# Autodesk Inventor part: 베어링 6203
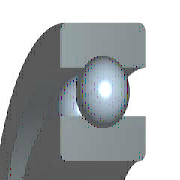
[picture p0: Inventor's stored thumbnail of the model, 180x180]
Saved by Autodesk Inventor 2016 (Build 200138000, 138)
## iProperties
IsCustomPart: 0
Created: 2016-04
Part Number: 베어링 6203
Material: 강철, 연강
Description: 깊은 그루브 볼 베어링
Document SubType Name: Modeling
Standard: KS B 2023
Designer: mdu
Standards Organization: KS
Language: ko-KR
Size Designation: 6203 - 17 x 40 x 12
Categories: <MemberInstance><Categories><Category DisplayName="샤프트 부품" InternalName="7f7aeb1f-a693-4053-b835-cee3144e0d98" Mnemonic="SHFT"><Category DisplayName="베어링" Inter
Density: 7.86 g/cm^3
Mass: 64.9809 g
Surface Area: 64.3582 cm^2
Volume: 8.26729 cm^3
Appearance: 노란색
Author: mdu
Revision Number: 1
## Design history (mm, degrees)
sketch "스케치" dims "d0" = 5.98 (= -0.26 x WD + 0.26 x BD)
  geometry: L1 (3.01, 14.25)-(8.99, 14.25); L2 (6, 14.25)-(6, 11.26); L3 (6, 14.25)-(6, 17.24); L4 (3.778, 12.249)-(0, 12.249); L5 (0, 8.5)-(12, 8.5); L6 (3.778, 16.251)-(0, 16.251); L7 (0, 20)-(12, 20); L8 (12, 8.5)-(12, 12.249); L9 (8.222, 12.249)-(12, 12.249); L10 (8.222, 16.251)-(12, 16.251); L11 (12, 20)-(12, 16.251); L12 (-1.4, 0)-(8.4, 0) reference; L13 (0, -0.3)-(0, 5.3) reference
  constraints: 22 end point, 4 point on line, 2 collinear, 2 perpendicular, 2 symmetric about line, 1 midpoint, 1 parallel, 14 other
  dimensions: "d9" = 17 diameter of L5 L12 (= WD); "d11" = 40 diameter of L7 L12 (= BD); "d12" = 12 distance between parallel lines of L8 L13 (= KB); "d13" = 24.498 diameter of L9 L12 (= 0.326 x BD + 0.674 x WD)
revolve "본체" stored, may be unused: angle "d6" = 90 deg
revolve "볼" stored, may be unused: angle "d7" = 90 deg
pattern_circular "IDS_ARRAYBALL[SIMPL:T]" dims angle "d3" = 360 deg
body "Solid1"
fillet "모깎기1" dims "d1" = 0.6 (= KRS)
other parameters: "WD" = 17 [user parameter; used in 5 equation terms], "BD" = 40 [user parameter; used in 5 equation terms], "KB" = 12 [user parameter; used in 1 equation term], "KRS" = 0.6 [user parameter; used in 1 equation term], "d4" = 0, "d5" = 0, "d8" = 0, "d14" = 0, "d15" = 0, "BBA" = 0 [user parameter], "BC0" = 4750000 [user parameter], "BC" = 9560000 [user parameter], "WR" = 8.5 (= 0.5 x WD) [user parameter]
